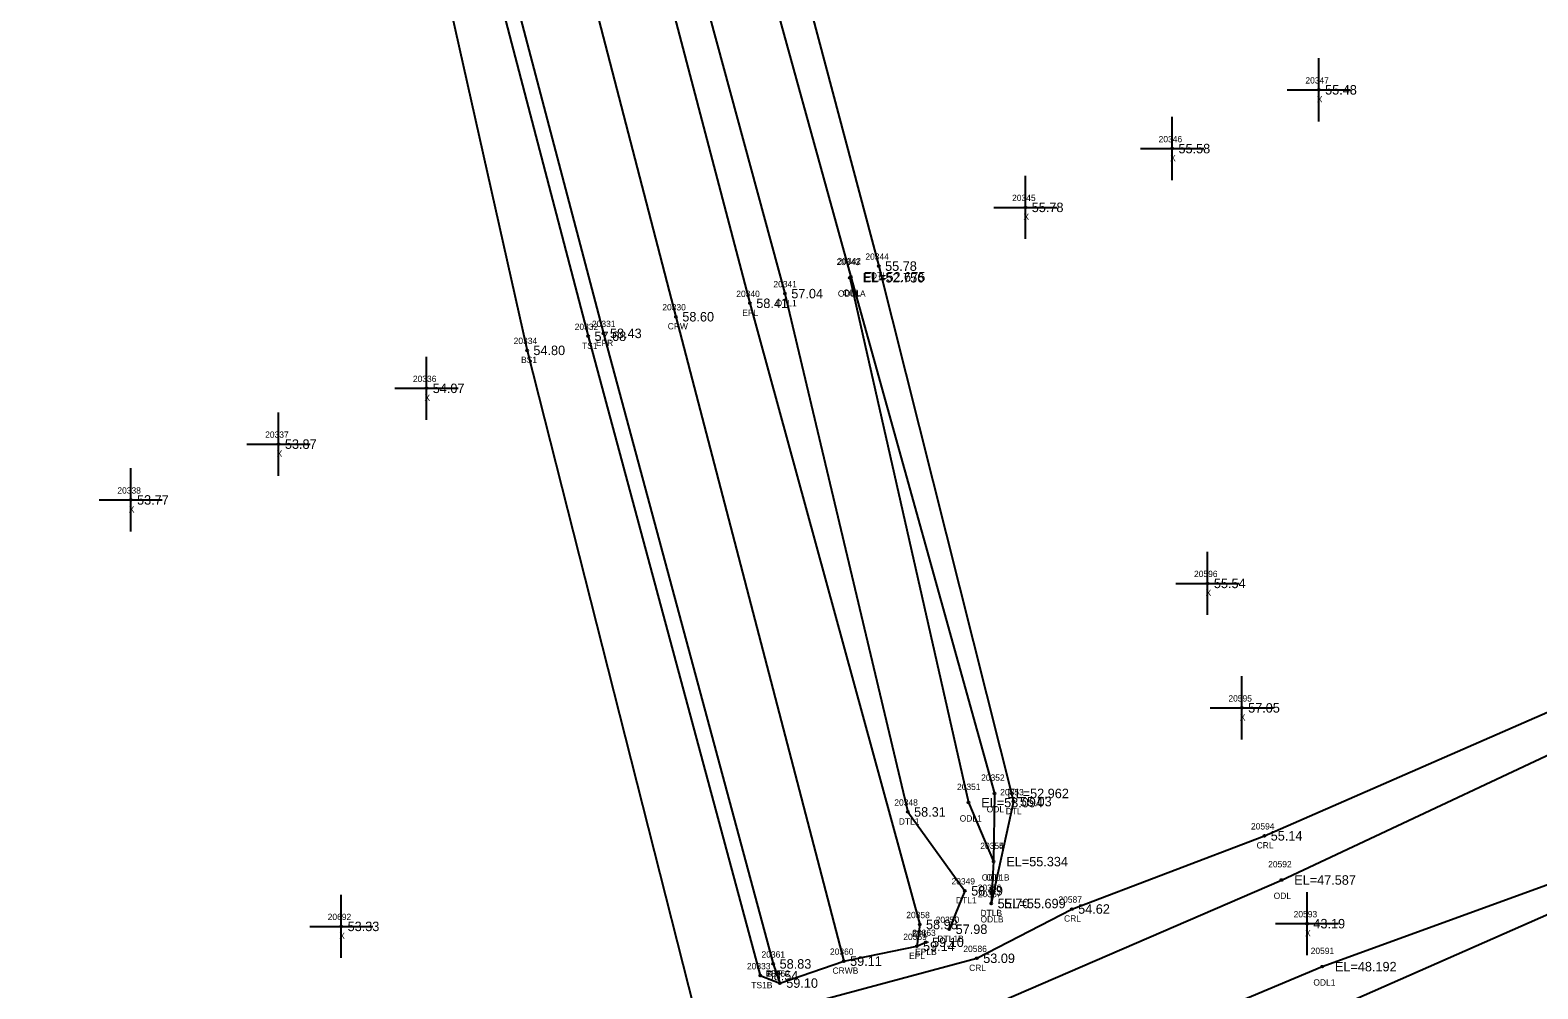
# Model space of a CAD drawing. Extents: x 2396547 to 2397655, y 770185 to 772649.
# Drawn here: x 2396920.4 to 2397158.9, y 771400.3 to 771552 of the extents above; entities that cross this region are included whole.
import ezdxf

# ---------------------------------------------------------------- set-up
doc = ezdxf.new("R2010")
doc.units = 0
for name, color, linetype in [('RD_DTM_BkLn1', 7, 'Continuous'), ('RD_DTM_BkLn2', 7, 'Continuous'), ('RD_DTM_BkLn_txCode', 7, 'Continuous'), ('RD_EX_H2O', 7, 'Continuous'), ('RD_EX_H2O_txCode', 7, 'Continuous'), ('RD_EX_Misc', 7, 'Continuous'), ('RD_EX_Misc_txCode', 7, 'Continuous'), ('RD_EX_Road', 7, 'Continuous'), ('RD_EX_Road_txCode', 7, 'Continuous'), ('RD_EX_TX_H2O_ELEV', 7, 'Continuous'), ('RD_EX_TX_Misc_ELEV', 7, 'Continuous'), ('RD_EX_TX_Road_ELEV', 7, 'Continuous'), ('RD_HC_Survey_ELEV', 7, 'Continuous'), ('RD_HC_Survey_txCode', 7, 'Continuous'), ('RD_SMD_Locator', 7, 'Continuous')]:
    doc.layers.add(name, color=color, linetype=linetype)

msp = doc.modelspace()

# ---------------------------------------------------------------- linework, layer by layer
at = {"layer": 'RD_DTM_BkLn1'}
msp.add_lwpolyline([(2396669.86, 772614.94), (2396704.28, 772521.49), (2396739.29, 772426.89), (2396775.36, 772328.69), (2396800.21, 772259.35), (2396825.58, 772185.8), (2396852.46, 772104.52), (2396872.48, 772041.55), (2396897.57, 771959.72), (2396918.76, 771888.68), (2396939.09, 771818.34), (2396959.29, 771747.62), (2396993.72, 771617.68), (2397022.56, 771506.67), (2397049.1, 771404.69)], dxfattribs=at)
at = {"layer": 'RD_DTM_BkLn2'}
for points in [[(2396921.95, 771810.18), (2396943.94, 771743.58), (2396982.88, 771602.26), (2397008.66, 771503.58), (2397035.9, 771402.4)], [(2396921.95, 771810.18), (2396927.42, 771791.88), (2396939.93, 771742.16), (2396976.22, 771602.97), (2396999, 771501.35), (2397026.41, 771393.39)], [(2397035.9, 771402.4), (2397039, 771401.22), (2397049.1, 771404.69), (2397060.64, 771407.04)]]:
    msp.add_lwpolyline(points, dxfattribs=at)
at = {"layer": 'RD_EX_H2O'}
for points in [[(2397132.06, 771727.73), (2397069.65, 771707.99), (2397027.41, 771693.94), (2396997.29, 771683.71), (2397009.52, 771621.94), (2397039.8, 771510.33), (2397059.22, 771428.3), (2397068.26, 771415.82), (2397065.8, 771409.74)], [(2397133.23, 771725), (2397070.25, 771705.35), (2397027.65, 771692.13), (2397008.03, 771684.24), (2397003.46, 771682.97), (2397004.86, 771679.14), (2397019.55, 771624.25), (2397050.23, 771512.98), (2397072.95, 771431.23), (2397072.81, 771420.44), (2397072.44, 771413.81)], [(2397133.83, 771721.66), (2397071.25, 771701.52), (2397031.62, 771688.97), (2397008.91, 771681.79), (2397013.82, 771672.05), (2397025.11, 771625.88), (2397054.64, 771514.68), (2397075.97, 771429.94), (2397072.44, 771413.81)], [(2397026.41, 771393.39), (2397070.16, 771405.14), (2397085.18, 771412.94), (2397115.64, 771424.52), (2397174.69, 771450.34), (2397230.25, 771466.48), (2397283.24, 771491.48), (2397342.91, 771519.42), (2397408.89, 771536.24), (2397447.46, 771546.47), (2397469.5, 771549.6), (2397497.19, 771541.27), (2397541.1, 771500.79)], [(2397042.3, 771381.6), (2397067.83, 771395.64), (2397118.36, 771417.53), (2397176.74, 771444.94), (2397209.62, 771454.54), (2397231.6, 771461.44), (2397284.94, 771486.86), (2397344.87, 771514.98), (2397410.89, 771531.68), (2397447.35, 771543.38), (2397470.51, 771546.83), (2397496.21, 771538.83), (2397538.93, 771498.41)], [(2397029.25, 771363), (2397046.94, 771364.51), (2397071.53, 771381.48), (2397124.8, 771403.82), (2397183.53, 771425.21), (2397238.71, 771441.76), (2397294.15, 771464.26), (2397352.71, 771489.51), (2397415.81, 771518.52), (2397439.88, 771522.42), (2397486.58, 771521.99), (2397528.15, 771484.04)], [(2397041.52, 771355.95), (2397076.78, 771367.04), (2397074.45, 771374.78), (2397101.55, 771387.62), (2397127, 771397.33), (2397184.13, 771422.52), (2397239.58, 771440.33), (2397295.12, 771461.42), (2397353.86, 771487.36), (2397417.93, 771512.91), (2397437.51, 771516.93), (2397483.94, 771516.4), (2397526.36, 771480.62)], [(2397050.07, 771512.84), (2397068.85, 771429.78), (2397072.81, 771420.44)]]:
    msp.add_lwpolyline(points, dxfattribs=at)
at = {"layer": 'RD_EX_Misc'}
for p, q in [((2397124.25, 771537.58), (2397124.25, 771547.58)), ((2397119.25, 771542.58), (2397129.25, 771542.58)), ((2397101.05, 771528.28), (2397101.05, 771538.28)), ((2397096.05, 771533.28), (2397106.05, 771533.28)), ((2397077.84, 771518.98), (2397077.84, 771528.98)), ((2397072.84, 771523.98), (2397082.84, 771523.98)), ((2396983.08, 771490.34), (2396983.08, 771500.34)), ((2396978.08, 771495.34), (2396988.08, 771495.34)), ((2396959.69, 771481.51), (2396959.69, 771491.51)), ((2396954.69, 771486.51), (2396964.69, 771486.51)), ((2396936.3, 771472.68), (2396936.3, 771482.68)), ((2396931.3, 771477.68), (2396941.3, 771477.68)), ((2397106.65, 771459.47), (2397106.65, 771469.47)), ((2397101.65, 771464.47), (2397111.65, 771464.47)), ((2397112.07, 771439.77), (2397112.07, 771449.77)), ((2397107.07, 771444.77), (2397117.07, 771444.77)), ((2396969.61, 771405.19), (2396969.61, 771415.19)), ((2397122.39, 771405.62), (2397122.39, 771415.62)), ((2396964.61, 771410.19), (2396974.61, 771410.19)), ((2397117.39, 771410.62), (2397127.39, 771410.62))]:
    msp.add_line(p, q, dxfattribs=at)
at = {"layer": 'RD_EX_Road'}
for points in [[(2396680.92, 772617.84), (2396715.6, 772525.73), (2396750.68, 772430.62), (2396786.3, 772332.21), (2396811.38, 772263.31), (2396839.69, 772181.74), (2396863.75, 772109.83), (2396883.63, 772046.56), (2396889.54, 772027.11), (2396896.25, 772004.37), (2396904.34, 771978.33), (2396908.24, 771964.89), (2396921.74, 771919.68), (2396927.03, 771902.11), (2396950.2, 771821.74), (2396970.47, 771750.68), (2396978.33, 771721.29), (2396990.58, 771675.04), (2397004.94, 771620.49), (2397034.26, 771508.8), (2397061.11, 771410.49), (2397060.64, 771407.04), (2397062.07, 771407.67)], [(2396658.78, 772611.07), (2396693.37, 772516.9), (2396729.65, 772418.78), (2396760.7, 772333.11), (2396788.58, 772254.87), (2396814.65, 772181.57), (2396841.1, 772100.86), (2396861.19, 772037.76), (2396886.09, 771955.71), (2396907.15, 771884.49), (2396928.56, 771811.72), (2396947.65, 771744.09), (2396985.17, 771602.64), (2397011.11, 771504.04), (2397037.95, 771404.25), (2397039, 771401.22)]]:
    msp.add_lwpolyline(points, dxfattribs=at)
at = {"layer": 'RD_SMD_Locator'}
for centre in [(2397124.25, 771542.58), (2397101.05, 771533.28), (2397077.84, 771523.98), (2397054.64, 771514.68), (2397050.07, 771512.84), (2397050.23, 771512.98), (2397039.8, 771510.33), (2397034.26, 771508.8), (2397022.56, 771506.67), (2397008.66, 771503.58), (2397011.11, 771504.04), (2396999, 771501.35), (2396983.08, 771495.34), (2396959.69, 771486.51), (2396936.3, 771477.68), (2397106.65, 771464.47), (2397112.07, 771444.77), (2397072.95, 771431.23), (2397059.22, 771428.3), (2397068.85, 771429.78), (2397075.97, 771429.94), (2397115.64, 771424.52), (2397072.81, 771420.44), (2397072.81, 771420.44), (2397118.36, 771417.53), (2397068.26, 771415.82), (2397072.44, 771413.81), (2397072.44, 771413.81), (2397085.18, 771412.94), (2396969.61, 771410.19), (2397061.11, 771410.49), (2397065.8, 771409.74), (2397122.39, 771410.62), (2397060.64, 771407.04), (2397062.07, 771407.67), (2397049.1, 771404.69), (2397070.16, 771405.14), (2397035.9, 771402.4), (2397037.95, 771404.25), (2397124.8, 771403.82), (2397039, 771401.22)]:
    msp.add_circle(centre, 0.15, dxfattribs=at)

# ---------------------------------------------------------------- texts
at = {"layer": 'RD_DTM_BkLn_txCode'}
for s, p in [('20332', (2397006.54, 771504.58)), ('20334', (2396996.88, 771502.35)), ('TS1', (2397007.7, 771501.58)), ('BS1', (2396998.05, 771499.35)), ('20333', (2397033.79, 771403.4)), ('TS1B', (2397034.47, 771400.4))]:
    msp.add_text(s, height=1, dxfattribs=at).set_placement(p)
at = {"layer": 'RD_EX_H2O_txCode'}
for s, p in [('20344', (2397052.52, 771515.68)), ('20343', (2397047.95, 771514.84)), ('20342', (2397048.11, 771514.98)), ('20341', (2397037.97, 771511.33)), ('DTL', (2397053.39, 771512.68)), ('ODL1A', (2397048.17, 771509.84)), ('ODL', (2397048.99, 771509.98)), ('DTL1', (2397038.39, 771508.33)), ('20352', (2397070.83, 771433.23)), ('20351', (2397067.02, 771431.78)), ('20353', (2397073.85, 771430.94)), ('20348', (2397057.1, 771429.3)), ('ODL', (2397071.71, 771428.23)), ('DTL', (2397074.72, 771427.94)), ('DTL1', (2397057.81, 771426.3)), ('ODL1', (2397067.44, 771426.78)), ('20594', (2397113.52, 771425.52)), ('20354', (2397070.7, 771422.44)), ('20355', (2397070.7, 771422.44)), ('CRL', (2397114.41, 771422.52)), ('20592', (2397116.24, 771419.53)), ('20349', (2397066.14, 771416.82)), ('20356', (2397070.3, 771415.81)), ('ODL1B', (2397070.93, 771417.44)), ('ODL', (2397071.57, 771417.44)), ('DTL1', (2397066.85, 771413.82)), ('20357', (2397070.33, 771414.81)), ('20587', (2397083.06, 771413.94)), ('ODL', (2397117.11, 771414.53)), ('20350', (2397063.64, 771410.74)), ('ODLB', (2397070.73, 771410.81)), ('DTLB', (2397070.73, 771411.81)), ('CRL', (2397083.95, 771410.94)), ('DTL1B', (2397063.92, 771407.74)), ('20586', (2397068.02, 771406.14)), ('20591', (2397122.97, 771405.82)), ('CRL', (2397068.93, 771403.14)), ('ODL1', (2397123.39, 771400.82))]:
    msp.add_text(s, height=1, dxfattribs=at).set_placement(p)
at = {"layer": 'RD_EX_Misc_txCode'}
for s, p in [('20347', (2397122.13, 771543.58)), ('X', (2397123.94, 771540.58)), ('20346', (2397098.91, 771534.28)), ('X', (2397100.73, 771531.28)), ('20345', (2397075.73, 771524.98)), ('X', (2397077.53, 771521.98)), ('20336', (2396980.94, 771496.34)), ('X', (2396982.77, 771493.34)), ('20337', (2396957.57, 771487.51)), ('X', (2396959.38, 771484.51)), ('20338', (2396934.19, 771478.68)), ('X', (2396935.99, 771475.68)), ('20596', (2397104.51, 771465.47)), ('X', (2397106.34, 771462.47)), ('20595', (2397109.95, 771445.77)), ('X', (2397111.75, 771442.77)), ('20692', (2396967.46, 771411.19)), ('20593', (2397120.27, 771411.62)), ('X', (2397122.08, 771408.62)), ('X', (2396969.29, 771408.19))]:
    msp.add_text(s, height=1, dxfattribs=at).set_placement(p)
at = {"layer": 'RD_EX_Road_txCode'}
for s, p in [('20340', (2397032.1, 771509.8)), ('EPL', (2397033.05, 771506.8)), ('20331', (2397009.27, 771505.04)), ('EPR', (2397009.88, 771502.04)), ('20358', (2397058.99, 771411.49)), ('20363', (2397059.93, 771408.67)), ('EPL', (2397059.91, 771408.49)), ('20359', (2397058.52, 771408.04)), ('20361', (2397036.09, 771405.25)), ('EPL', (2397059.43, 771405.04)), ('EPLB', (2397060.39, 771405.67)), ('EPR', (2397036.72, 771402.25)), ('20362', (2397036.86, 771402.22))]:
    msp.add_text(s, height=1, dxfattribs=at).set_placement(p)
at = {"layer": 'RD_EX_TX_H2O_ELEV'}
for s, p in [('55.78', (2397055.64, 771513.93)), ('EL=52.756', (2397052.07, 771512.09)), ('EL=52.675', (2397052.23, 771512.23)), ('57.04', (2397040.8, 771509.58)), ('EL=52.962', (2397074.95, 771430.48)), ('58.31', (2397060.22, 771427.55)), ('EL=53.094', (2397070.85, 771429.03)), ('55.03', (2397076.97, 771429.19)), ('55.14', (2397116.64, 771423.77)), ('EL=55.334', (2397074.81, 771419.69)), ('EL=55.334', (2397074.81, 771419.69)), ('58.09', (2397069.26, 771415.07)), ('EL=47.587', (2397120.36, 771416.78)), ('55.70', (2397073.44, 771413.06)), ('EL=55.699', (2397074.44, 771413.06)), ('54.62', (2397086.18, 771412.19)), ('57.98', (2397066.8, 771408.99)), ('53.09', (2397071.16, 771404.39)), ('EL=48.192', (2397126.8, 771403.07))]:
    msp.add_text(s, height=1.5, dxfattribs=at).set_placement(p)
at = {"layer": 'RD_EX_TX_Misc_ELEV'}
for s, p in [('55.48', (2397125.25, 771541.83)), ('55.58', (2397102.05, 771532.53)), ('55.78', (2397078.84, 771523.23)), ('57.68', (2397009.66, 771502.83)), ('54.80', (2397000, 771500.6)), ('54.07', (2396984.08, 771494.59)), ('53.87', (2396960.69, 771485.76)), ('53.77', (2396937.3, 771476.93)), ('55.54', (2397107.65, 771463.72)), ('57.05', (2397113.07, 771444.02)), ('53.33', (2396970.61, 771409.44)), ('43.19', (2397123.39, 771409.87)), ('58.54', (2397036.9, 771401.65))]:
    msp.add_text(s, height=1.5, dxfattribs=at).set_placement(p)
at = {"layer": 'RD_EX_TX_Road_ELEV'}
for s, p in [('58.41', (2397035.26, 771508.05)), ('58.43', (2397012.11, 771503.29)), ('58.98', (2397062.11, 771409.74)), ('59.14', (2397061.64, 771406.29)), ('59.10', (2397063.07, 771406.92)), ('58.83', (2397038.95, 771403.5)), ('59.10', (2397040, 771400.47))]:
    msp.add_text(s, height=1.5, dxfattribs=at).set_placement(p)
at = {"layer": 'RD_HC_Survey_ELEV'}
for s, p in [('58.60', (2397023.56, 771505.92)), ('59.11', (2397050.1, 771403.94))]:
    msp.add_text(s, height=1.5, dxfattribs=at).set_placement(p)
at = {"layer": 'RD_HC_Survey_txCode'}
for s, p in [('20330', (2397020.4, 771507.67)), ('CRW', (2397021.25, 771504.67)), ('20360', (2397046.92, 771405.69)), ('CRWB', (2397047.32, 771402.69))]:
    msp.add_text(s, height=1, dxfattribs=at).set_placement(p)

doc.saveas('drawing.dxf')
